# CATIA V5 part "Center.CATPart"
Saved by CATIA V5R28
Part number: Center
Material "DS Yellow": density 7860 kg/m3, Young's modulus 2e+11 Pa, Poisson ratio 0.266
Bounding box of the stored display mesh (mm): x -28 to 28, y -16 to 34, z -28 to 28
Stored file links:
  C:\Users\Parisa\Desktop\tarah sanat\Universal Coupling\Center.CATPart
  C:\Program Files\Dassault Systemes\B28\win_b64\startup\materials\yellow_env_512x512.jpg
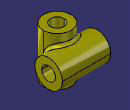
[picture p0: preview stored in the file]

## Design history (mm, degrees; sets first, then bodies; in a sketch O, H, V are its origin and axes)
Body1 "Center" (main body), material "DS Yellow"
  Sketch1 on xy-plane, origin (0, 0, 0), H (1, 0, 0), V (0, 1, 0)
    circle A1 centre (0, 0) radius 16
    radius A1 = 16
  Pad1: profile Sketch1, direction (0, 0, 1), length 28, mirrored extent
  Sketch2 on yz-plane, origin (0, 0, 0), H (0, 1, 0), V (0, 0, 1)
    circle A1 centre (18, 0) radius 16
    point P1 (18, 0)
    radius A1 = 16
    distance P1 V = 18
    coincidence: P1 H
  Pad2: profile Sketch2, direction (1, 0, 0), length 28, mirrored extent
  Sketch3 on xy-plane, origin (0, 0, 0), H (1, 0, 0), V (0, 1, 0)
    circle A1 centre (0, 0) radius 8
    radius A1 = 8
  Pocket1: profile Sketch3, direction (0, 0, -1), length 28, mirrored extent
  Sketch4 on yz-plane, origin (0, 0, 0), H (0, 1, 0), V (0, 0, 1)
    circle A1 centre (18, 0) radius 8
    point P1 (18, 0)
    radius A1 = 8
    distance P1 V = 18
    coincidence: P1 H
  Pocket2: profile Sketch4, direction (-1, 0, 0), length 28, mirrored extent
  Fillet1: radius 3, on edge [face of Pad1 from Sketch1.A1 | face of Pad2 from Sketch2.A1]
